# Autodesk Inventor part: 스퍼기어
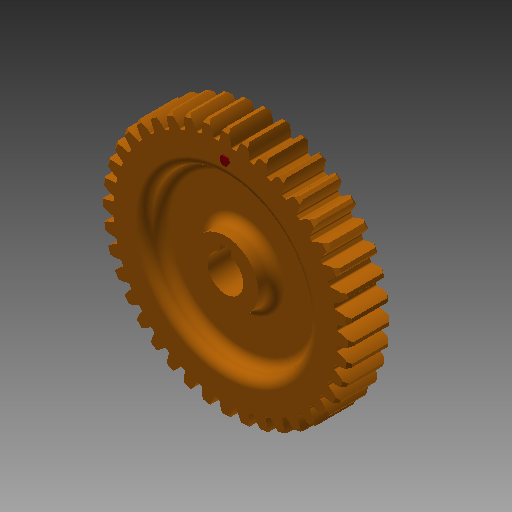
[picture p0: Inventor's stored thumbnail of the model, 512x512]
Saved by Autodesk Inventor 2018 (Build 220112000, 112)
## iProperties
Created: 2019-01
Part Number: 스퍼기어
Material: 알루미늄 6061
Document SubType Name: Modeling
Designer: mduedu
Density: 2.71 g/cm^3
Mass: 157.226 g
Surface Area: 186.47 cm^2
Volume: 58.017 cm^3
Appearance: 주황색
Author: mduedu
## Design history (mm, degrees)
sketch "스케치1"
  geometry: C1 r 37.5 at (0, 0); C2 r 40 at (0, 0); C3 r 42 at (0, 0); 1 further point
  constraints: 3 centre point, 3 coincident
  dimensions: "d0" = 75 diameter of C1; "d2" = 80 diameter of C2; "d3" = 84 diameter of C3
extrude "돌출1" new body sketch "스케치1" distance "d4" = 14; taper "d5" = 0 deg
sketch "스케치2"
  geometry: L1 (0, 0)-(-42, 0); L2 (0, 0)-(0, 42); L3 (-0.57, 0)-(-0.57, 41.996); L4 (-1.57, 0)-(-1.57, 39.969); L5 (-2.07, 0)-(-2.07, 37.443); A1 r 42 centre (0, 0) between (-42, 0) and (0, 42) reference; A2 r 9.223 centre (7.138, 36.933) between (-0.57, 41.996) and (-2.07, 37.443); A3 r 9.223 centre (-7.138, 36.933) between (2.07, 37.443) and (0.57, 41.996); A4 r 37.5 centre (0, 0) between (2.07, 37.443) and (-2.07, 37.443); A5 r 42 centre (0, 0) between (0.57, 41.996) and (-0.57, 41.996); 2 further points
  constraints: 12 point on circle, 10 end point, 4 centre point, 3 parallel, 3 symmetric about line, 2 coincident, 1 horizontal, 1 perpendicular, 5 other
  dimensions: "d6" = 0.5 distance between parallel lines of L4 L5; "d8" = 1 distance between parallel lines of L3 L4; "d9" = 1.57 distance between parallel lines of L2 L4
extrude "돌출2" join sketch "스케치2" stored distance "d10" = 14; taper "d11" = 0 deg
chamfer "모따기1" distance "d12" = 1; stored, may be unused: second distance "d13" = 2, angle "d14" = 45 deg
fillet "모깎기1" dims "d15" = 0.5
sketch "스케치3"
  geometry: C1 r 11 at (0, 0); 1 further point
  constraints: 1 centre point, 1 coincident
  dimensions: "d19" = 22 diameter of C1
extrude "돌출3" join sketch "스케치3" distance "d20" = 7; taper "d21" = 0 deg
fillet "모깎기2" dims "d22" = 3
sketch "스케치4"
  geometry: C1 r 11 at (0, 0); C2 r 27.5 at (0, 0); 1 further point
  constraints: 2 centre point, 2 coincident
  dimensions: "d23" = 22 diameter of C1; "d24" = 55 diameter of C2
extrude "돌출4" cut sketch "스케치4" distance "d25" = 6; taper "d26" = 0 deg
fillet "모깎기3" dims "d27" = 3
sketch "스케치5" dims "d28" = 66
  geometry: C1 r 1.5 at (0, 33); 2 further points
  constraints: 2 vertical alignment, 1 centre point, 1 coincident, 2 other
  dimensions: "d29" = 3 diameter of C1
extrude "돌출5" join sketch "스케치5" distance "d30" = 0.5; taper "d31" = 0 deg
sketch "스케치6"
  geometry: L1 (-2, 5.657)-(2, 5.657); L2 (2, 5.657)-(2, 7.8); L3 (2, 7.8)-(-2, 7.8); L4 (-2, 7.8)-(-2, 5.657); A1 r 6 centre (0, 0) between (-2, 5.657) and (2, 5.657); 1 further point
  constraints: 8 end point, 2 parallel, 2 point on circle, 1 centre point, 1 coincident, 1 horizontal, 1 perpendicular
  dimensions: "d32" = 13.8 dimension on A1 L3; "d34" = 4 distance of L2.end L3.end; "d35" = 12 diameter of A1
extrude "돌출6" cut sketch "스케치6" extent not by distance; stored distance "d36" = 0.5; taper "d37" = 0 deg
chamfer "모따기2" distance "d38" = 1; stored, may be unused: second distance "d39" = 2, angle "d40" = 45 deg
node "솔리드1"
pattern_circular "원형 패턴1" dims angle "d17" = 360 deg
